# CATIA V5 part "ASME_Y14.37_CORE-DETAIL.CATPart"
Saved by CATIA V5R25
Part number: ASME_Y14.37_CORE_DETAIL-103
Bounding box of the stored display mesh (mm): x -1012.309 to 1278.04, y -788.718 to 818.501, z 0 to 49.022
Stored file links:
  \\NW\Data\MSE-Composites\STEP Interoperability\ExampleData\ASME_Y14.37 Test Parts\ASSEMBLY VERSION\ASME_Y14.37_CORE-DETAIL.CATPart
  C:\Users\jvl2147\Desktop\CompositesCatalog.CATMaterial
  \\Nw\787lib\787-PROCINT-WKG\Dom_SSDBS\DM\!!ShareFileForWritingServices\Composites\Standards and References\ASMEY-14.37\ASMEY-14.37_COMPOSITES.CATMaterial
  C:\Program Files\Dassault Systemes\B25SP2PRALL\win_b64\startup\materials\honeycomb.jpg
  \\Nw\787lib\787-PROCINT-WKG\Dom_SSDBS\DM\!!ShareFileForWritingServices\Composites\Standards and References\ASME Y14.37\PLY TABEL_-1 BOND ASSEMBLY.xlsx
  \\Nw\787lib\787-PROCINT-WKG\Dom_SSDBS\DM\!!ShareFileForWritingServices\Composites\Standards and References\ASME Y14.37\ASME_Y14.37_VALIDATION-PROPERTIES_CORE STIFFENED BOND PART.xlsx.xlsx
  C:\Users\jvl2147\AppData\Local\Temp\Copy (2) of CA_ASME_Y14.37_CORE-STIFFENED-BOND-PART.CATPart
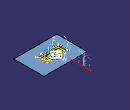
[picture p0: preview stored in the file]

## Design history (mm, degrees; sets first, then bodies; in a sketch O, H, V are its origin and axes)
Parameters
  StandardPlyThickness = 0.254 mm
  `Scale Value` = 100
CompParametersFeature1 "CATCoParametersFeatName": Value 0, Value 45, Value -45, Value 90, Orientations 999.999, Orientations 90
CompStacking1 "Stacking"
CompReviewTools1 "Review tools"
f4a2d38f3ddc11d3a929006094b99c4b_11 "CATTPSSet"
TTRSSet1
Toolside_View1 "CATTPSView"
Set1 "CONSTRUCTION (REF)"
  Sketch1 on XY plane of AxisSystem2, origin (0, 0, 0), H (1, 0, 0), V (0, 1, 0)
    line L1 (-1012.309, 818.5005) -> (1278.0398, 818.5005)
    line L2 (1278.0398, 818.5005) -> (1278.0398, -788.7181)
    line L3 (1278.0398, -788.7181) -> (-1012.309, -788.7181)
    line L4 (-1012.309, -788.7181) -> (-1012.309, 818.5005)
    horizontal: L1 H, L3 H
    vertical: L2 V, L4 V
  Fill1: Boundary Sketch1
  CurvePar1: Offset CompStdContourFeature1, Support Fill1, Offset2 0, Offset1 50.8
  Plane1: type Offset, RefPlane YZ plane of AxisSystem2, Offset -598
  Plane2: type Offset, RefPlane YZ plane of AxisSystem2, Offset -598, reversed
  Plane3: type Offset, RefPlane ZX plane of AxisSystem2, Offset -292
  Plane4: type Offset, RefPlane ZX plane of AxisSystem2, Offset -292, reversed
  MultiSel1
  CompStdContourFeature1 "CATCoStdContourFeatName": SupportSurface Fill1, ClosedSetOfCurves ({intersect ToIntersect1 Plane2, ToIntersect2 Fill1}; {intersect ToIntersect1 Plane3, ToIntersect2 Fill1}; {intersect ToIntersect1 Plane1, ToIntersect2 Fill1}; {intersect ToIntersect1 Plane4, ToIntersect2 Fill1}), ExtrapolDist 0.2
  Plane5: type Offset, RefPlane Plane2, Offset 254, reversed
  Intersect1: ToIntersect1 Plane5, ToIntersect2 Fill1
  Plane6: type Offset, RefPlane Plane1, Offset 254
  Intersect2: ToIntersect1 Plane6, ToIntersect2 Fill1
  Plane7: type Offset, RefPlane ZX plane of AxisSystem2, Offset -50.8
  CurvePar2: Offset CompStdContourFeature1, Offset2 0, Offset1 139.7
  Point1: (0, 0, 0), in AxisSystem2
  AxisSystem1: origin (0, 0, -127), X (1, 0, 0), Y (0, 1, 0), Z (0, 0, 1)
  Point2: (215.6851, 77.4411, 0)
  Point3: type OnCurve, Support edge [ZX plane of AxisSystem2 | YZ plane of AxisSystem2], Length 127
  Point4: type OnPlane, Support Join1, H -130.714, V 273.957, Direction (1, 0, 0)
  Split1: ToCut Circle1, Cutting {intersect ToIntersect1 Plane4, ToIntersect2 Fill1}
  Circle1: type CtrRad, Start 0, End 180, Center Point4, Support Join1, Radius 76.2, FirstDirection (1, 0, 0)
Set2 "ENGINEERING GEOMETRY"
  Join1 "TOOLSIDE SURFACE": Elements Fill1
  AxisSystem2 "PLY ORIENTATION COORDINATE SYSTEM": origin (0, 0, 0), X (1, 0, 0), Y (0, 1, 0), Z (0, 0, 1)
Body1 "CORE-103" (main body)
  CompCoreSolidFormGeometry1 "Geometry_8": Curves CurvePar1, ReferenceSurface Fill1, VariableOffsets 0, VariableSlopes 20, BasicHeight 25.4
